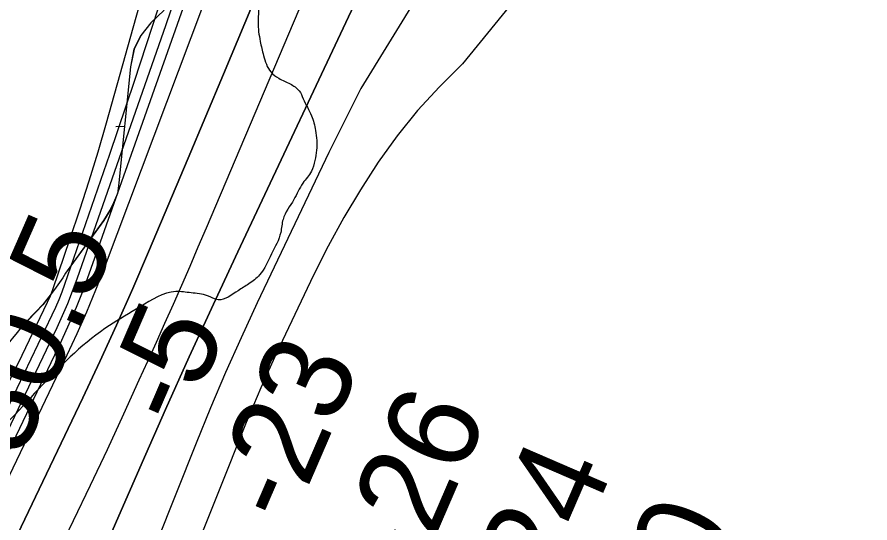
# Model space of a CAD drawing. Extents: x 3297716 to 3335574, y 688621 to 713991.
# Drawn here: x 3320230 to 3320855, y 695242 to 695612 of the extents above; entities that cross this region are included whole.
import ezdxf

# ---------------------------------------------------------------- set-up
doc = ezdxf.new("R2010")
doc.units = 0
for name, color, linetype in [('V-RIVR-EDGE', 7, 'Continuous'), ('V-RIVR-RANG', 7, 'Continuous'), ('V-SITE-VEGE', 7, 'Continuous'), ('V-TOPO-DPTH', 7, 'Continuous'), ('V-TOPO-MAJR', 7, 'Continuous'), ('V-TOPO-MINR', 7, 'Continuous'), ('V-TOPO-WATR', 7, 'Continuous'), ('V-WETL-SWMP', 7, 'Continuous')]:
    doc.layers.add(name, color=color, linetype=linetype)

msp = doc.modelspace()

# ---------------------------------------------------------------- linework, layer by layer
at = {"layer": 'V-RIVR-EDGE'}
msp.add_spline([(3321618.45, 701061.3), (3321639.17, 701040.92), (3321661.92, 701020.55), (3321674.32, 701007.67), (3321694.16, 700986.07), (3321717.72, 700957.41), (3321720.61, 700953.26), (3321724.75, 700950.76), (3321726.82, 700949.51), (3321730.12, 700946.19), (3321742.93, 700927.09), (3321753.65, 700905.93), (3321756.11, 700893.9), (3321759.81, 700884.36), (3321768.06, 700867.34), (3321776.73, 700853.23), (3321786.64, 700837.46), (3321794.49, 700827.9), (3321804.41, 700817.1), (3321812.69, 700810.04), (3321821.8, 700809.18), (3321830.09, 700806.68), (3321833.39, 700803.77), (3321835.87, 700798.79), (3321840.83, 700792.97), (3321849.52, 700787.56), (3321852, 700783.83), (3321866.46, 700765.14), (3321875.54, 700751.02), (3321880.08, 700741.06), (3321885.01, 700725.72), (3321889.55, 700717), (3321895.75, 700710.35), (3321901.94, 700699.15), (3321908.12, 700684.63), (3321912.22, 700664.31), (3321919.16, 700623.67), (3321922, 700598.79), (3321922.33, 700564.8), (3321921.8, 700517.55), (3321919.28, 700502.22), (3321912.99, 700476.13), (3321905.84, 700433.04), (3321899.49, 700379.59), (3321893.61, 700348.1), (3321887.31, 700316.2), (3321880.2, 700288.86), (3321874.74, 700259.03), (3321869.25, 700218.84), (3321863.73, 700164.56), (3321860.77, 700141.35), (3321859.51, 700133.9), (3321857.38, 700109.86), (3321857.72, 700080.85), (3321854.3, 700038.58), (3321847.95, 699987.61), (3321847.83, 699937.46), (3321848.6, 699913.83), (3321849.33, 699873.21), (3321853.78, 699830.51), (3321854.96, 699803.15), (3321853.26, 699786.99), (3321851.54, 699762.54), (3321847.36, 699747.63), (3321844.45, 699743.9), (3321843.17, 699728.57), (3321839.41, 699718.22), (3321831.1, 699708.71), (3321827.36, 699705.81), (3321826.94, 699701.67), (3321826.9, 699687.16), (3321823.15, 699678.88), (3321813.6, 699670.62), (3321798.66, 699664.44), (3321785.76, 699644.16), (3321779.93, 699632.57), (3321773.21, 699598.6), (3321768.1, 699540.58), (3321765.15, 699519.86), (3321762.59, 699492.93), (3321757.53, 699458.54), (3321751.27, 699439.49), (3321741.26, 699415.47), (3321732.08, 699391.04), (3321722.08, 699368.27), (3321716.24, 699354.61), (3321712.46, 699334.72), (3321711.17, 699313.17), (3321708.16, 699269.24), (3321710.2, 699258.88), (3321713.08, 699250.99), (3321718.86, 699240.62), (3321727.54, 699231.89), (3321733.75, 699226.9), (3321735.8, 699219.85), (3321729.5, 699186.29), (3321720.32, 699159.37), (3321709.07, 699134.53), (3321700.31, 699115.49), (3321685.36, 699100.6), (3321679.12, 699094.4), (3321674.96, 699087.37), (3321674.54, 699083.64), (3321670.34, 699063.75), (3321660.32, 699031.86), (3321651.17, 699018.62), (3321638.28, 699002.49), (3321632.02, 698987.58), (3321625.76, 698968.12), (3321619.46, 698936.22), (3321615.66, 698908.04), (3321607.29, 698875.32), (3321593.49, 698825.61), (3321583.49, 698805.33), (3321580.14, 698792.07), (3321580.11, 698777.57), (3321580.08, 698768.03), (3321572.16, 698748.16), (3321567.94, 698717.91), (3321559.1, 698663.64), (3321555.74, 698647.06), (3321554.07, 698638.36), (3321550.73, 698631.74), (3321551.53, 698617.65), (3321548.59, 698601.9), (3321548.13, 698586.15), (3321543.97, 698577.46), (3321538.14, 698566.28), (3321534.37, 698551.37), (3321535.17, 698541.42), (3321533.49, 698532.72), (3321521.4, 698502.08), (3321503.45, 698451.14), (3321490.53, 698421.75), (3321481.38, 698409.33), (3321476.81, 698403.96), (3321474.3, 698395.26), (3321466.79, 698374.55), (3321458.45, 698355.09), (3321454.28, 698343.91), (3321453.02, 698339.36), (3321455.92, 698336.45), (3321456.74, 698333.13), (3321454.65, 698329.4), (3321448.83, 698321.96), (3321440.11, 698313.69), (3321430.98, 698308.32), (3321420.6, 698301.3), (3321418.1, 698296.34), (3321412.68, 698284.33), (3321407.28, 698277.71), (3321395.61, 698252.46), (3321375.16, 698198.21), (3321359.31, 698158.46), (3321345.97, 698126.16), (3321337.19, 698093.85), (3321334.25, 698078.94), (3321334.23, 698070.24), (3321336.69, 698059.45), (3321328.74, 698032.12), (3321314.56, 697996.09), (3321306.62, 697968.76), (3321301.21, 697958.41), (3321293.31, 697951.38), (3321284.15, 697933.99), (3321274.57, 697915.37), (3321271.23, 697904.6), (3321272.45, 697893.82), (3321272.42, 697881.8), (3321266.57, 697862.33), (3321256.95, 697828.37), (3321254.44, 697817.6), (3321249.85, 697808.08), (3321241.51, 697787.79), (3321233.61, 697774.54), (3321226.53, 697762.13), (3321220.27, 697745.56), (3321216.1, 697733.97), (3321215.67, 697727.34), (3321217.73, 697725.67), (3321219.8, 697723.6), (3321219.37, 697718.62), (3321208.12, 697691.71), (3321197.7, 697668.11), (3321194.79, 697666.04), (3321191.06, 697666.05), (3321191.45, 697656.52), (3321188.95, 697651.55), (3321185.63, 697649.07), (3321180.24, 697647.84), (3321181.04, 697635.82), (3321179.37, 697630.85), (3321174.8, 697625.89), (3321172.29, 697619.26), (3321170.2, 697612.22), (3321164.33, 697585.71), (3321162.65, 697577.01), (3321158.92, 697575.78), (3321154.35, 697570.81), (3321148.51, 697557.56), (3321144.77, 697550.53), (3321143.91, 697539.34), (3321140.58, 697535.62), (3321134.77, 697529.41), (3321132.68, 697525.27), (3321128.5, 697509.53), (3321122.64, 697486.75), (3321103.06, 697447.42), (3321100.98, 697441.63), (3321100.95, 697432.92), (3321091.79, 697415.12), (3321084.3, 697404.36), (3321071.4, 697382.01), (3321064.34, 697376.64), (3321056.87, 697372.93), (3321048.14, 697363.42), (3321041.07, 697351), (3321031.9, 697332.37), (3321023.56, 697312.08), (3321015.63, 697288.06), (3321006.43, 697254.51), (3320994.76, 697229.67), (3320983.51, 697207.32), (3320979.36, 697203.6), (3320975.6, 697193.66), (3320968.09, 697172.54), (3320962.64, 697145.61), (3320955.95, 697122.42), (3320943.84, 697086.8), (3320940.48, 697069.4), (3320936.31, 697061.12), (3320926.34, 697048.71), (3320920.93, 697043.34), (3320909.64, 697002.33), (3320899.61, 696969.2), (3320887.51, 696935.24), (3320880.84, 696920.33), (3320879.58, 696912.46), (3320883.28, 696900.43), (3320882.85, 696894.63), (3320876.18, 696878.07), (3320871.56, 696854.04), (3320866.95, 696835.81), (3320859.86, 696815.94), (3320857.35, 696806.82), (3320853.17, 696794.4), (3320849.83, 696784.46), (3320847.3, 696766.64), (3320843.13, 696755.46), (3320836.06, 696746.78), (3320830.23, 696736.43), (3320825.62, 696714.06), (3320819.78, 696699.98), (3320814.39, 696700.82), (3320813.53, 696688.39), (3320798.51, 696648.22), (3320788.51, 696625.45), (3320782.7, 696621.73), (3320776.44, 696606.83), (3320773.11, 696599.38), (3320766.05, 696592.76), (3320752.32, 696573.31), (3320739.41, 696550.14), (3320720.25, 696512.05), (3320700.68, 696473.55), (3320668.58, 696401.51), (3320646.49, 696351.83), (3320619.82, 696291.38), (3320606.9, 696264.05), (3320587.72, 696216.85), (3320576.88, 696191.59), (3320559.79, 696152.26), (3320552.68, 696128.24), (3320546.41, 696106.29), (3320536.39, 696076.47), (3320526.77, 696040.43), (3320506.73, 695984.11), (3320462.47, 695850.34), (3320450.34, 695806.02), (3320441.99, 695784.08), (3320420.24, 695702.06), (3320413.95, 695672.23), (3320409.31, 695639.92), (3320408.02, 695624.17), (3320406.74, 695608.42), (3320408.37, 695594.32), (3320410.83, 695583.96), (3320416.18, 695571.92), (3320421.98, 695567.35), (3320430.26, 695563.18), (3320436.88, 695558.19), (3320439.76, 695552.38), (3320445.95, 695539.93), (3320448.82, 695529.15), (3320449.62, 695514.64), (3320448.35, 695507.18), (3320445.85, 695499.32), (3320439.61, 695490.63), (3320432.95, 695478.62), (3320425.04, 695464.14), (3320423.36, 695454.61), (3320416.68, 695438.87), (3320407.94, 695423.56), (3320400.05, 695416.95), (3320392.16, 695411.99), (3320377.64, 695405.4), (3320369.77, 695408.32), (3320357.76, 695410.42), (3320346.57, 695411.28), (3320320.43, 695400.15), (3320298.01, 695386.53), (3320249, 695343.13), (3320201.63, 695295.58), (3320188.34, 695286.49), (3320177.97, 695282.37), (3320168.43, 695279.5), (3320163.44, 695274.95), (3320158.02, 695258.8), (3320150.48, 695228.14), (3320140.07, 695207.45), (3320125.48, 695174.32), (3320115.05, 695149.48), (3320110.04, 695134.99), (3320108.37, 695129.6), (3320108.36, 695125.87), (3320112.48, 695115.91), (3320113.71, 695108.45), (3320113.28, 695102.65), (3320106.62, 695091.47), (3320104.12, 695086.92), (3320100.38, 695081.54), (3320098.3, 695077.82), (3320098.29, 695074.91), (3320104.89, 695063.71), (3320105.7, 695055.41), (3320108.15, 695041.32), (3320112.69, 695030.11), (3320122.19, 695016.41), (3320128.39, 695010.18), (3320133.76, 695004.36), (3320135.82, 694999.39), (3320135.81, 694993.17), (3320132.46, 694981.16), (3320110.39, 694941.42), (3320095, 694917.83), (3320080.04, 694902.95), (3320068.41, 694893.44), (3320055.95, 694881.45), (3320033.07, 694848.77), (3319991.89, 694787.94), (3319966.93, 694752.36), (3319939.88, 694710.15), (3319919.91, 694678.69), (3319900.35, 694647.24), (3319884.95, 694618.27), (3319831.21, 694511.88), (3319802.89, 694453.92), (3319782.47, 694411.28), (3319716.3, 694301.19), (3319680.91, 694240.35), (3319651.35, 694187.37), (3319580.16, 694059.05), (3319556.78, 694017.46)], degree=3, dxfattribs=at)
at = {"layer": 'V-SITE-VEGE'}
for p, q in [((3320338.12, 695617.1), (3320328.27, 695607.78)), ((3320328.27, 695607.78), (3320320.98, 695598.52)), ((3320320.98, 695598.52), (3320316, 695588.58)), ((3320316, 695588.58), (3320313.36, 695575.6)), ((3320313.36, 695575.6), (3320304.81, 695490.83)), ((3320304.81, 695490.83), (3320303.84, 695483.15)), ((3320303.84, 695483.15), (3320300.4, 695474.41)), ((3320300.4, 695474.41), (3320298.42, 695470.93)), ((3320298.42, 695470.93), (3320293.79, 695463.26)), ((3320293.79, 695463.26), (3320265.83, 695424.81)), ((3320265.83, 695424.81), (3320263.85, 695421.33)), ((3320263.85, 695421.33), (3320257.87, 695412.94)), ((3320257.87, 695412.94), (3320249.19, 695401.75)), ((3320249.19, 695401.75), (3320233.1, 695384.88)), ((3320230.43, 695381.38), (3320222.42, 695371.57)), ((3320233.1, 695384.88), (3320230.43, 695381.38))]:
    msp.add_line(p, q, dxfattribs=at)
at = {"layer": 'V-TOPO-DPTH'}
for points in [[(3320110.86, 694983.76), (3320278.54, 695333.63), (3320291.01, 695360.14), (3320303.24, 695386.76), (3320315.09, 695413.55), (3320326.7, 695440.45), (3320355.69, 695508.98), (3320381.48, 695570.28), (3320407.09, 695631.66), (3320432.43, 695693.15), (3320457.61, 695754.71), (3320558.08, 696001.89), (3320565.4, 696019.7), (3320572.83, 696037.47), (3320580.41, 696055.17), (3320588.09, 696072.84), (3320617.98, 696140.83)], [(3320110.86, 694983.76), (3320278.54, 695333.63), (3320291.01, 695360.14), (3320303.24, 695386.76), (3320315.09, 695413.55), (3320326.7, 695440.45), (3320355.69, 695508.98), (3320381.48, 695570.28), (3320407.09, 695631.66), (3320432.43, 695693.15), (3320457.61, 695754.71), (3320558.08, 696001.89), (3320565.4, 696019.7), (3320572.83, 696037.47), (3320580.41, 696055.17), (3320588.09, 696072.84), (3320617.98, 696140.83)], [(3320041.64, 694646.14), (3320322.02, 695286.33), (3320339.15, 695325), (3320356.48, 695363.58), (3320374.11, 695402.01), (3320391.96, 695440.35), (3320482.93, 695633.72), (3320512.98, 695695.85), (3320543.93, 695757.51), (3320576.21, 695818.49), (3320609.38, 695879.02), (3320641.41, 695935.99), (3320658.84, 695967.88), (3320675.73, 696000.04), (3320691.84, 696032.61), (3320707.42, 696065.44), (3320707.54, 696065.71), (3320722.25, 696099.09), (3320736.24, 696132.76)], [(3320736.24, 696132.76), (3320722.25, 696099.09), (3320707.54, 696065.71), (3320707.42, 696065.44), (3320691.84, 696032.61), (3320675.73, 696000.04), (3320658.84, 695967.88), (3320641.41, 695935.99), (3320609.38, 695879.02), (3320576.21, 695818.49), (3320543.93, 695757.51), (3320512.98, 695695.85), (3320482.93, 695633.72), (3320391.96, 695440.35), (3320374.11, 695402.01), (3320356.48, 695363.58), (3320339.15, 695325), (3320322.02, 695286.33), (3320041.64, 694646.14)], [(3320521.59, 696113.45), (3320507.09, 696075.77), (3320504.76, 696069.5), (3320502.51, 696063.21), (3320500.4, 696056.87), (3320498.38, 696050.49), (3320480.75, 695992.8), (3320469.75, 695957.63), (3320458.45, 695922.56), (3320446.69, 695887.65), (3320434.63, 695852.83), (3320283.01, 695424.16), (3320278.43, 695411.84), (3320273.6, 695399.64), (3320268.38, 695387.59), (3320262.9, 695375.65), (3320100.76, 695036.46)], [(3320870.64, 695963.25), (3320556.47, 695577.81), (3320539.55, 695561.09), (3320523.47, 695543.65), (3320508.64, 695525.14), (3320494.64, 695505.9), (3320481.75, 695485.86), (3320469.47, 695465.46), (3320458.13, 695444.53), (3320447.41, 695423.24), (3320420.11, 695365.88), (3320414.33, 695353.41), (3320408.7, 695340.87), (3320403.32, 695328.21), (3320398.1, 695315.49), (3320356.22, 695210.53)], [(3320870.64, 695963.25), (3320556.47, 695577.81), (3320539.55, 695561.09), (3320523.47, 695543.65), (3320508.64, 695525.14), (3320494.64, 695505.9), (3320481.75, 695485.86), (3320469.47, 695465.46), (3320458.13, 695444.53), (3320447.41, 695423.24), (3320420.11, 695365.88), (3320414.33, 695353.41), (3320408.7, 695340.87), (3320403.32, 695328.21), (3320398.1, 695315.49), (3320356.22, 695210.53)]]:
    msp.add_lwpolyline(points, dxfattribs=at)
at = {"layer": 'V-TOPO-MAJR'}
msp.add_lwpolyline([(3320462.07, 696115.05), (3320450.88, 696082.14), (3320440.51, 696048.96), (3320430.69, 696015.6), (3320295.59, 695534.6), (3320289.4, 695513.28), (3320282.97, 695492.04), (3320276.18, 695470.91), (3320269.14, 695449.86), (3320256.31, 695412.58), (3320254.56, 695407.93), (3320252.53, 695403.39), (3320233.79, 695364.49), (3320223.13, 695342.91), (3320212.17, 695321.48), (3320200.79, 695300.27), (3320189.11, 695279.22), (3319865.6, 694709.41)], dxfattribs=at)
at = {"layer": 'V-TOPO-MINR'}
for points in [[(3320911.56, 696448.03), (3320764.65, 696019.55), (3320482.03, 695559.91), (3320458.61, 695513.15), (3320406.21, 695403.03), (3320394.42, 695377.62), (3320382.95, 695352.06), (3320371.99, 695326.29), (3320361.36, 695300.37), (3320274.56, 695082.82)], [(3320531.03, 696190.14), (3320496.23, 696099.68), (3320490.64, 696084.64), (3320485.3, 696069.51), (3320480.31, 696054.26), (3320475.57, 696038.93), (3320438.69, 695914.5), (3320415.13, 695837.07), (3320390.82, 695759.89), (3320365.39, 695683.06), (3320339.21, 695606.48), (3320274.06, 695420.31), (3320270.74, 695411.32), (3320267.23, 695402.41), (3320263.43, 695393.61), (3320259.43, 695384.9), (3320184.28, 695228.11)], [(3320736.24, 696132.76), (3320722.25, 696099.09), (3320707.54, 696065.71), (3320707.42, 696065.44), (3320691.84, 696032.61), (3320675.73, 696000.04), (3320658.84, 695967.88), (3320641.41, 695935.99), (3320609.38, 695879.02), (3320576.21, 695818.49), (3320543.93, 695757.51), (3320512.98, 695695.85), (3320482.93, 695633.72), (3320391.96, 695440.35), (3320374.11, 695402.01), (3320356.48, 695363.58), (3320339.15, 695325), (3320322.02, 695286.33), (3320041.64, 694646.14)], [(3320485.16, 696123.68), (3320476.43, 696099.82), (3320468.09, 696075.82), (3320460.36, 696051.63), (3320453.02, 696027.3), (3320366.34, 695726.53), (3320350.3, 695672.48), (3320333.68, 695618.61), (3320316.21, 695565.01), (3320298.16, 695511.6), (3320265.16, 695416.45), (3320263.09, 695410.79), (3320260.89, 695405.17), (3320258.5, 695399.64), (3320255.97, 695394.15), (3320209.6, 695297.63), (3320183.25, 695244.21), (3320156.18, 695191.17)], [(3320558.54, 696114.91), (3320544.23, 696084.02), (3320530.48, 696052.89), (3320517.59, 696021.39), (3320505.27, 695989.65), (3320493.35, 695957.74), (3320481.41, 695925.84), (3320469.45, 695893.95), (3320457.45, 695862.06), (3320294.14, 695428.47), (3320287.82, 695412.34), (3320281.23, 695396.32), (3320274.22, 695380.48), (3320266.94, 695364.76), (3320003.63, 694814.92)], [(3320521.59, 696113.45), (3320507.09, 696075.77), (3320504.76, 696069.5), (3320502.51, 696063.21), (3320500.4, 696056.87), (3320498.38, 696050.49), (3320480.75, 695992.8), (3320469.75, 695957.63), (3320458.45, 695922.56), (3320446.69, 695887.65), (3320434.63, 695852.83), (3320283.01, 695424.16), (3320278.43, 695411.84), (3320273.6, 695399.64), (3320268.38, 695387.59), (3320262.9, 695375.65), (3320100.76, 695036.46)], [(3320585.99, 695969.18), (3320368.73, 695457.74), (3320362.76, 695443.76), (3320356.74, 695429.79), (3320350.67, 695415.85), (3320344.56, 695401.93), (3320338.39, 695388.04), (3320332.18, 695374.16), (3320325.92, 695360.3), (3320319.62, 695346.46), (3320308.33, 695321.77), (3320296.24, 695295.66), (3320284, 695269.62), (3320271.53, 695243.68), (3320258.9, 695217.82)], [(3320870.64, 695963.25), (3320556.47, 695577.81), (3320539.55, 695561.09), (3320523.47, 695543.65), (3320508.64, 695525.14), (3320494.64, 695505.9), (3320481.75, 695485.86), (3320469.47, 695465.46), (3320458.13, 695444.53), (3320447.41, 695423.24), (3320420.11, 695365.88), (3320414.33, 695353.41), (3320408.7, 695340.87), (3320403.32, 695328.21), (3320398.1, 695315.49), (3320356.22, 695210.53)]]:
    msp.add_lwpolyline(points, dxfattribs=at)
at = {"layer": 'V-TOPO-WATR'}
msp.add_lwpolyline([(3320617.98, 696140.83), (3320588.09, 696072.84), (3320580.41, 696055.17), (3320572.83, 696037.47), (3320565.4, 696019.7), (3320558.08, 696001.89), (3320457.61, 695754.71), (3320432.43, 695693.15), (3320407.09, 695631.66), (3320381.48, 695570.28), (3320355.69, 695508.98), (3320326.7, 695440.45), (3320315.09, 695413.55), (3320303.24, 695386.76), (3320291.01, 695360.14), (3320278.54, 695333.63), (3320110.86, 694983.76)], dxfattribs=at)
at = {"layer": 'V-WETL-SWMP'}
for p, q in [((3320338.09, 695617.12), (3320328.25, 695607.79)), ((3320328.25, 695607.79), (3320320.95, 695598.53)), ((3320320.95, 695598.53), (3320315.97, 695588.59)), ((3320315.97, 695588.59), (3320313.32, 695575.61)), ((3320313.32, 695575.61), (3320304.78, 695490.84)), ((3320302.77, 695532.17), (3320308.95, 695532.18)), ((3320304.78, 695490.84), (3320303.81, 695483.16)), ((3320303.81, 695483.16), (3320300.37, 695474.42)), ((3320300.37, 695474.42), (3320298.39, 695470.94)), ((3320298.39, 695470.94), (3320293.76, 695463.27)), ((3320293.76, 695463.27), (3320265.8, 695424.82)), ((3320265.8, 695424.82), (3320263.82, 695421.34)), ((3320263.82, 695421.34), (3320257.83, 695412.96)), ((3320257.83, 695412.96), (3320251.83, 695405.26)), ((3320251.83, 695405.26), (3320249.16, 695401.76)), ((3320249.16, 695401.76), (3320244.47, 695396.84)), ((3320241.78, 695394.03), (3320233.07, 695384.89)), ((3320244.47, 695396.84), (3320241.78, 695394.03)), ((3320233.07, 695384.89), (3320230.4, 695381.39))]:
    msp.add_line(p, q, dxfattribs=at)

# ---------------------------------------------------------------- texts
at = {"layer": 'V-RIVR-RANG'}
for s, rotation, p in [('30.5', 66.34833, (3320233.19, 695287.69)), ('-5', 66.62747, (3320352.38, 695309.94)), ('-23', 66.62747, (3320430.68, 695239.05)), ('-26', 66.62747, (3320523.63, 695202.06)), ('-24', 66.62747, (3320615.43, 695162.4)), ('-20', 66.62747, (3320706.71, 695121.54))]:
    msp.add_text(s, height=67, rotation=rotation, dxfattribs=at).set_placement(p)

doc.saveas('drawing.dxf')
